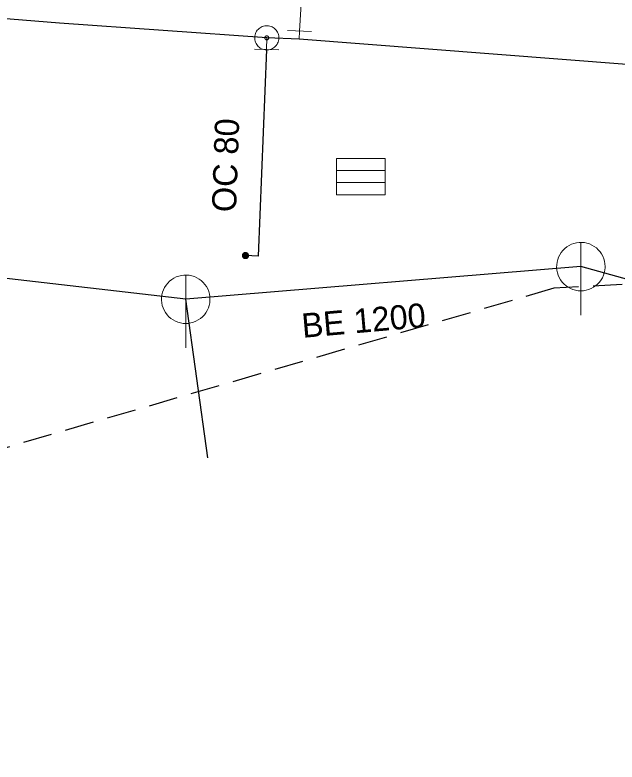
# Model space of a CAD drawing. Extents: x -725643 to -725418, y -978375 to -978221.
# Drawn here: x -725526.82 to -725501.98, y -978371.93 to -978341.11 of the extents above; entities that cross this region are included whole.
import ezdxf

# ---------------------------------------------------------------- set-up
doc = ezdxf.new("R2010")
doc.units = 0
doc.header["$LTSCALE"] = 0.4
doc.linetypes.add('MEDIUM_DASHED', pattern=[4.5, 3, -1.5])
doc.layers.add('1', color=7, linetype='Continuous')
for name, color, linetype, lineweight in [('13', 7, 'Continuous', 13), ('14', 7, 'Continuous', 25), ('17', 7, 'Continuous', 25), ('22', 7, 'Continuous', 13), ('34', 7, 'Continuous', 13), ('47', 7, 'Continuous', 13), ('63', 7, 'MEDIUM_DASHED', 25), ('9', 7, 'Continuous', 13)]:
    doc.layers.add(name, color=color, linetype=linetype, lineweight=lineweight)

msp = doc.modelspace()

# ---------------------------------------------------------------- linework, layer by layer
at = {"layer": '13'}
msp.add_line((-725515.079, -978341.78), (-725514.594, -978332.899), dxfattribs=at)
at = {"layer": '14', "lineweight": 13}
for p, q in [((-725515.094, -978342.114), (-725515.079, -978341.78)), ((-725516.432, -978342.059), (-725516.44, -978342.541))]:
    msp.add_line(p, q, dxfattribs=at)
at = {"layer": '14'}
for p, q in [((-725448.203, -978366.647), (-725503.472, -978351.493)), ((-725518.866, -978359.379), (-725519.776, -978352.842))]:
    msp.add_line(p, q, dxfattribs=at)
msp.add_lwpolyline([(-725503.472, -978351.493), (-725519.776, -978352.842), (-725535.414, -978351.036)], dxfattribs=at)
at = {"layer": '17'}
for points in [[(-725516.432, -978342.059), (-725524.989, -978341.46), (-725545.003, -978339.812), (-725548.553, -978340.172), (-725550.989, -978339.387)], [(-725476.788, -978344.909), (-725498.899, -978343.37), (-725515.094, -978342.114), (-725516.432, -978342.059)], [(-725516.44, -978342.541), (-725516.789, -978351.069), (-725517.309, -978351.039)]]:
    msp.add_lwpolyline(points, dxfattribs=at)
at = {"layer": '22'}
for p, q in [((-725513.552, -978347.532), (-725511.552, -978347.532)), ((-725513.552, -978348.032), (-725511.552, -978348.032)), ((-725503.471, -978353.493), (-725503.47, -978350.493)), ((-725519.776, -978354.842), (-725519.775, -978351.842))]:
    msp.add_line(p, q, dxfattribs=at)
for points in [[(-725513.552, -978347.032), (-725511.552, -978347.032), (-725511.552, -978348.532), (-725513.552, -978348.532)], [(-725502.471, -978351.493), (-725502.476, -978351.384), (-725502.494, -978351.276), (-725502.524, -978351.17), (-725502.564, -978351.069), (-725502.616, -978350.972), (-725502.678, -978350.882), (-725502.75, -978350.799), (-725502.83, -978350.725), (-725502.918, -978350.659), (-725503.012, -978350.604), (-725503.112, -978350.559), (-725503.217, -978350.526), (-725503.324, -978350.504), (-725503.433, -978350.494), (-725503.543, -978350.496), (-725503.651, -978350.51), (-725503.758, -978350.535), (-725503.861, -978350.572), (-725503.959, -978350.621), (-725504.051, -978350.679), (-725504.137, -978350.748), (-725504.214, -978350.825), (-725504.283, -978350.911), (-725504.342, -978351.003), (-725504.39, -978351.101), (-725504.427, -978351.204), (-725504.453, -978351.311), (-725504.467, -978351.419), (-725504.47, -978351.529), (-725504.46, -978351.638), (-725504.439, -978351.745), (-725504.405, -978351.849), (-725504.361, -978351.949), (-725504.306, -978352.044), (-725504.24, -978352.132), (-725504.166, -978352.212), (-725504.083, -978352.284), (-725503.993, -978352.346), (-725503.897, -978352.398), (-725503.795, -978352.439), (-725503.69, -978352.469), (-725503.582, -978352.487), (-725503.472, -978352.493), (-725503.363, -978352.487), (-725503.255, -978352.469), (-725503.15, -978352.44), (-725503.048, -978352.399), (-725502.951, -978352.347), (-725502.861, -978352.285), (-725502.778, -978352.214), (-725502.703, -978352.134), (-725502.638, -978352.046), (-725502.582, -978351.952), (-725502.538, -978351.852), (-725502.504, -978351.748), (-725502.482, -978351.64), (-725502.472, -978351.531)], [(-725518.776, -978352.842), (-725518.781, -978352.733), (-725518.799, -978352.625), (-725518.829, -978352.519), (-725518.869, -978352.418), (-725518.921, -978352.321), (-725518.983, -978352.231), (-725519.055, -978352.148), (-725519.135, -978352.074), (-725519.223, -978352.008), (-725519.317, -978351.953), (-725519.417, -978351.908), (-725519.522, -978351.875), (-725519.629, -978351.853), (-725519.738, -978351.843), (-725519.848, -978351.845), (-725519.956, -978351.859), (-725520.063, -978351.884), (-725520.166, -978351.921), (-725520.264, -978351.97), (-725520.356, -978352.028), (-725520.442, -978352.097), (-725520.519, -978352.174), (-725520.588, -978352.26), (-725520.647, -978352.352), (-725520.695, -978352.45), (-725520.732, -978352.553), (-725520.758, -978352.66), (-725520.772, -978352.768), (-725520.775, -978352.878), (-725520.765, -978352.987), (-725520.744, -978353.094), (-725520.71, -978353.198), (-725520.666, -978353.298), (-725520.611, -978353.393), (-725520.545, -978353.481), (-725520.471, -978353.561), (-725520.388, -978353.633), (-725520.298, -978353.695), (-725520.202, -978353.747), (-725520.1, -978353.788), (-725519.995, -978353.818), (-725519.887, -978353.836), (-725519.777, -978353.842), (-725519.668, -978353.836), (-725519.56, -978353.818), (-725519.455, -978353.789), (-725519.353, -978353.748), (-725519.256, -978353.696), (-725519.166, -978353.634), (-725519.083, -978353.563), (-725519.008, -978353.483), (-725518.943, -978353.395), (-725518.887, -978353.301), (-725518.843, -978353.201), (-725518.809, -978353.097), (-725518.787, -978352.989), (-725518.777, -978352.88)]]:
    msp.add_lwpolyline(points, close=True, dxfattribs=at)
at = {"layer": '34'}
for p, q in [((-725515.578, -978341.758), (-725514.579, -978341.802)), ((-725515.94, -978342.56), (-725516.939, -978342.52))]:
    msp.add_line(p, q, dxfattribs=at)
at = {"layer": '47'}
for points in [[(-725516.931, -978342.038), (-725516.93, -978342.09), (-725516.924, -978342.142), (-725516.912, -978342.193), (-725516.896, -978342.243), (-725516.874, -978342.291), (-725516.847, -978342.336), (-725516.816, -978342.377), (-725516.78, -978342.416), (-725516.742, -978342.45), (-725516.699, -978342.481), (-725516.653, -978342.507), (-725516.605, -978342.527), (-725516.555, -978342.543), (-725516.504, -978342.553), (-725516.452, -978342.558), (-725516.4, -978342.557), (-725516.348, -978342.551), (-725516.296, -978342.539), (-725516.247, -978342.523), (-725516.199, -978342.501), (-725516.154, -978342.474), (-725516.112, -978342.443), (-725516.073, -978342.407), (-725516.039, -978342.369), (-725516.009, -978342.326), (-725515.983, -978342.28), (-725515.962, -978342.232), (-725515.947, -978342.182), (-725515.937, -978342.131), (-725515.932, -978342.079), (-725515.933, -978342.027), (-725515.939, -978341.975), (-725515.95, -978341.923), (-725515.967, -978341.874), (-725515.989, -978341.826), (-725516.015, -978341.781), (-725516.046, -978341.739), (-725516.082, -978341.7), (-725516.121, -978341.666), (-725516.164, -978341.636), (-725516.21, -978341.61), (-725516.257, -978341.589), (-725516.308, -978341.574), (-725516.359, -978341.564), (-725516.411, -978341.559), (-725516.463, -978341.56), (-725516.515, -978341.566), (-725516.566, -978341.577), (-725516.616, -978341.594), (-725516.664, -978341.616), (-725516.709, -978341.642), (-725516.75, -978341.673), (-725516.789, -978341.709), (-725516.823, -978341.748), (-725516.854, -978341.791), (-725516.88, -978341.837), (-725516.9, -978341.884), (-725516.916, -978341.935), (-725516.926, -978341.986)], [(-725516.513, -978342.055), (-725516.514, -978342.064), (-725516.512, -978342.072), (-725516.51, -978342.08), (-725516.508, -978342.088), (-725516.504, -978342.097), (-725516.499, -978342.104), (-725516.495, -978342.111), (-725516.489, -978342.117), (-725516.482, -978342.122), (-725516.475, -978342.128), (-725516.468, -978342.132), (-725516.46, -978342.135), (-725516.452, -978342.138), (-725516.444, -978342.14), (-725516.435, -978342.14), (-725516.426, -978342.141), (-725516.418, -978342.139), (-725516.41, -978342.137), (-725516.402, -978342.135), (-725516.393, -978342.131), (-725516.386, -978342.126), (-725516.379, -978342.122), (-725516.373, -978342.116), (-725516.367, -978342.109), (-725516.362, -978342.102), (-725516.358, -978342.095), (-725516.355, -978342.087), (-725516.352, -978342.079), (-725516.35, -978342.071), (-725516.35, -978342.062), (-725516.349, -978342.053), (-725516.351, -978342.045), (-725516.353, -978342.037), (-725516.355, -978342.029), (-725516.359, -978342.02), (-725516.363, -978342.013), (-725516.368, -978342.006), (-725516.374, -978342), (-725516.381, -978341.994), (-725516.388, -978341.989), (-725516.395, -978341.985), (-725516.403, -978341.982), (-725516.411, -978341.979), (-725516.419, -978341.977), (-725516.428, -978341.977), (-725516.437, -978341.976), (-725516.445, -978341.978), (-725516.453, -978341.98), (-725516.461, -978341.982), (-725516.47, -978341.986), (-725516.477, -978341.99), (-725516.484, -978341.995), (-725516.49, -978342.001), (-725516.495, -978342.008), (-725516.501, -978342.015), (-725516.505, -978342.022), (-725516.508, -978342.03), (-725516.511, -978342.038), (-725516.513, -978342.046)]]:
    msp.add_lwpolyline(points, close=True, dxfattribs=at)
at = {"layer": '63'}
msp.add_lwpolyline([(-725440.663, -978348.762), (-725504.582, -978352.39), (-725504.582, -978352.39), (-725528.587, -978359.368), (-725528.587, -978359.368), (-725551.474, -978371.929), (-725551.474, -978371.929), (-725566.826, -978360.206), (-725566.826, -978360.206), (-725557.894, -978328.944), (-725533.89, -978332.573), (-725533.89, -978332.573), (-725529.424, -978311.918), (-725529.424, -978311.918), (-725514.351, -978316.105), (-725514.351, -978316.105), (-725517.422, -978329.502), (-725517.422, -978329.502), (-725504.582, -978332.573), (-725504.582, -978332.573), (-725495.092, -978321.408)], dxfattribs=at)
at = {"layer": '9'}
for points in [[(-725517.435, -978351.039), (-725517.435, -978351.052), (-725517.433, -978351.065), (-725517.43, -978351.078), (-725517.425, -978351.09), (-725517.419, -978351.102), (-725517.412, -978351.113), (-725517.404, -978351.123), (-725517.394, -978351.133), (-725517.384, -978351.141), (-725517.373, -978351.148), (-725517.361, -978351.154), (-725517.349, -978351.159), (-725517.336, -978351.162), (-725517.323, -978351.164), (-725517.31, -978351.166), (-725517.297, -978351.165), (-725517.284, -978351.163), (-725517.271, -978351.16), (-725517.259, -978351.155), (-725517.247, -978351.149), (-725517.236, -978351.142), (-725517.226, -978351.134), (-725517.216, -978351.124), (-725517.208, -978351.114), (-725517.201, -978351.103), (-725517.195, -978351.091), (-725517.19, -978351.079), (-725517.187, -978351.066), (-725517.185, -978351.053), (-725517.183, -978351.04), (-725517.184, -978351.027), (-725517.186, -978351.014), (-725517.189, -978351.001), (-725517.194, -978350.989), (-725517.2, -978350.977), (-725517.207, -978350.966), (-725517.215, -978350.956), (-725517.225, -978350.946), (-725517.235, -978350.938), (-725517.246, -978350.931), (-725517.258, -978350.925), (-725517.27, -978350.92), (-725517.283, -978350.917), (-725517.296, -978350.915), (-725517.309, -978350.914), (-725517.322, -978350.914), (-725517.335, -978350.916), (-725517.348, -978350.919), (-725517.36, -978350.924), (-725517.372, -978350.93), (-725517.383, -978350.937), (-725517.393, -978350.945), (-725517.403, -978350.955), (-725517.411, -978350.965), (-725517.418, -978350.976), (-725517.424, -978350.988), (-725517.429, -978351), (-725517.432, -978351.013), (-725517.434, -978351.026)], [(-725517.415, -978351.039), (-725517.416, -978351.05), (-725517.414, -978351.061), (-725517.411, -978351.072), (-725517.407, -978351.082), (-725517.402, -978351.092), (-725517.396, -978351.101), (-725517.389, -978351.11), (-725517.381, -978351.118), (-725517.372, -978351.125), (-725517.363, -978351.131), (-725517.353, -978351.136), (-725517.343, -978351.14), (-725517.332, -978351.143), (-725517.321, -978351.146), (-725517.31, -978351.146), (-725517.299, -978351.146), (-725517.288, -978351.144), (-725517.277, -978351.141), (-725517.267, -978351.137), (-725517.257, -978351.132), (-725517.248, -978351.126), (-725517.239, -978351.119), (-725517.231, -978351.111), (-725517.224, -978351.102), (-725517.218, -978351.093), (-725517.213, -978351.083), (-725517.209, -978351.073), (-725517.206, -978351.062), (-725517.204, -978351.051), (-725517.203, -978351.04), (-725517.203, -978351.029), (-725517.205, -978351.018), (-725517.208, -978351.007), (-725517.212, -978350.997), (-725517.217, -978350.987), (-725517.223, -978350.978), (-725517.23, -978350.969), (-725517.238, -978350.961), (-725517.247, -978350.954), (-725517.256, -978350.948), (-725517.266, -978350.943), (-725517.276, -978350.939), (-725517.287, -978350.936), (-725517.298, -978350.934), (-725517.309, -978350.934), (-725517.32, -978350.933), (-725517.331, -978350.935), (-725517.342, -978350.938), (-725517.352, -978350.942), (-725517.362, -978350.947), (-725517.371, -978350.953), (-725517.38, -978350.96), (-725517.388, -978350.968), (-725517.395, -978350.977), (-725517.401, -978350.986), (-725517.406, -978350.996), (-725517.41, -978351.006), (-725517.413, -978351.017), (-725517.415, -978351.028)], [(-725517.396, -978351.039), (-725517.396, -978351.048), (-725517.395, -978351.057), (-725517.392, -978351.066), (-725517.389, -978351.074), (-725517.385, -978351.082), (-725517.38, -978351.09), (-725517.374, -978351.097), (-725517.368, -978351.103), (-725517.361, -978351.109), (-725517.353, -978351.114), (-725517.345, -978351.118), (-725517.337, -978351.121), (-725517.328, -978351.124), (-725517.319, -978351.125), (-725517.31, -978351.127), (-725517.301, -978351.126), (-725517.292, -978351.125), (-725517.283, -978351.122), (-725517.275, -978351.119), (-725517.267, -978351.115), (-725517.259, -978351.11), (-725517.252, -978351.104), (-725517.246, -978351.098), (-725517.24, -978351.091), (-725517.235, -978351.083), (-725517.231, -978351.075), (-725517.228, -978351.067), (-725517.225, -978351.058), (-725517.224, -978351.049), (-725517.222, -978351.04), (-725517.223, -978351.031), (-725517.224, -978351.022), (-725517.227, -978351.013), (-725517.23, -978351.005), (-725517.234, -978350.997), (-725517.239, -978350.989), (-725517.245, -978350.982), (-725517.251, -978350.976), (-725517.258, -978350.97), (-725517.266, -978350.965), (-725517.274, -978350.961), (-725517.282, -978350.958), (-725517.291, -978350.955), (-725517.3, -978350.954), (-725517.309, -978350.953), (-725517.318, -978350.953), (-725517.327, -978350.954), (-725517.336, -978350.957), (-725517.344, -978350.96), (-725517.352, -978350.964), (-725517.36, -978350.969), (-725517.367, -978350.975), (-725517.373, -978350.981), (-725517.379, -978350.988), (-725517.384, -978350.996), (-725517.388, -978351.004), (-725517.391, -978351.012), (-725517.394, -978351.021), (-725517.395, -978351.03)], [(-725517.376, -978351.039), (-725517.376, -978351.046), (-725517.375, -978351.053), (-725517.374, -978351.06), (-725517.371, -978351.066), (-725517.368, -978351.072), (-725517.364, -978351.078), (-725517.36, -978351.084), (-725517.355, -978351.089), (-725517.349, -978351.093), (-725517.343, -978351.097), (-725517.337, -978351.1), (-725517.331, -978351.103), (-725517.324, -978351.104), (-725517.317, -978351.107), (-725517.31, -978351.107), (-725517.303, -978351.107), (-725517.296, -978351.105), (-725517.289, -978351.104), (-725517.283, -978351.101), (-725517.276, -978351.098), (-725517.271, -978351.094), (-725517.265, -978351.09), (-725517.26, -978351.085), (-725517.256, -978351.079), (-725517.252, -978351.073), (-725517.249, -978351.067), (-725517.246, -978351.061), (-725517.244, -978351.054), (-725517.243, -978351.047), (-725517.242, -978351.04), (-725517.242, -978351.033), (-725517.243, -978351.026), (-725517.245, -978351.019), (-725517.248, -978351.013), (-725517.251, -978351.006), (-725517.255, -978351.001), (-725517.259, -978350.995), (-725517.264, -978350.99), (-725517.27, -978350.986), (-725517.275, -978350.982), (-725517.282, -978350.979), (-725517.288, -978350.976), (-725517.295, -978350.974), (-725517.302, -978350.973), (-725517.309, -978350.973), (-725517.316, -978350.973), (-725517.323, -978350.973), (-725517.33, -978350.975), (-725517.336, -978350.978), (-725517.342, -978350.981), (-725517.348, -978350.985), (-725517.354, -978350.989), (-725517.359, -978350.994), (-725517.363, -978351), (-725517.367, -978351.005), (-725517.37, -978351.012), (-725517.373, -978351.018), (-725517.374, -978351.025), (-725517.376, -978351.032)], [(-725517.356, -978351.039), (-725517.356, -978351.044), (-725517.356, -978351.049), (-725517.355, -978351.054), (-725517.353, -978351.058), (-725517.351, -978351.063), (-725517.348, -978351.067), (-725517.345, -978351.07), (-725517.341, -978351.074), (-725517.338, -978351.077), (-725517.334, -978351.08), (-725517.329, -978351.082), (-725517.325, -978351.084), (-725517.32, -978351.085), (-725517.315, -978351.087), (-725517.31, -978351.087), (-725517.305, -978351.087), (-725517.3, -978351.086), (-725517.295, -978351.085), (-725517.291, -978351.083), (-725517.286, -978351.081), (-725517.282, -978351.078), (-725517.278, -978351.075), (-725517.275, -978351.071), (-725517.272, -978351.068), (-725517.269, -978351.064), (-725517.267, -978351.059), (-725517.265, -978351.055), (-725517.264, -978351.05), (-725517.263, -978351.045), (-725517.262, -978351.04), (-725517.262, -978351.035), (-725517.263, -978351.03), (-725517.264, -978351.025), (-725517.266, -978351.021), (-725517.268, -978351.016), (-725517.271, -978351.012), (-725517.274, -978351.008), (-725517.277, -978351.005), (-725517.281, -978351.002), (-725517.285, -978350.999), (-725517.29, -978350.997), (-725517.294, -978350.995), (-725517.299, -978350.994), (-725517.304, -978350.993), (-725517.309, -978350.993), (-725517.314, -978350.993), (-725517.319, -978350.994), (-725517.324, -978350.994), (-725517.328, -978350.996), (-725517.333, -978350.998), (-725517.337, -978351.001), (-725517.34, -978351.004), (-725517.344, -978351.007), (-725517.347, -978351.011), (-725517.35, -978351.015), (-725517.352, -978351.02), (-725517.354, -978351.024), (-725517.355, -978351.029), (-725517.356, -978351.034)], [(-725517.336, -978351.039), (-725517.336, -978351.042), (-725517.337, -978351.045), (-725517.336, -978351.047), (-725517.335, -978351.05), (-725517.334, -978351.053), (-725517.332, -978351.055), (-725517.33, -978351.057), (-725517.328, -978351.059), (-725517.326, -978351.061), (-725517.324, -978351.063), (-725517.321, -978351.065), (-725517.318, -978351.066), (-725517.316, -978351.066), (-725517.313, -978351.067), (-725517.31, -978351.067), (-725517.307, -978351.067), (-725517.304, -978351.067), (-725517.301, -978351.066), (-725517.299, -978351.065), (-725517.296, -978351.064), (-725517.294, -978351.062), (-725517.291, -978351.06), (-725517.289, -978351.058), (-725517.288, -978351.056), (-725517.286, -978351.054), (-725517.285, -978351.051), (-725517.283, -978351.048), (-725517.283, -978351.046), (-725517.282, -978351.043), (-725517.281, -978351.04), (-725517.282, -978351.037), (-725517.282, -978351.034), (-725517.283, -978351.031), (-725517.284, -978351.029), (-725517.285, -978351.026), (-725517.287, -978351.024), (-725517.288, -978351.021), (-725517.29, -978351.019), (-725517.293, -978351.018), (-725517.295, -978351.016), (-725517.298, -978351.015), (-725517.3, -978351.014), (-725517.303, -978351.013), (-725517.306, -978351.013), (-725517.309, -978351.012), (-725517.312, -978351.013), (-725517.315, -978351.012), (-725517.317, -978351.014), (-725517.32, -978351.014), (-725517.323, -978351.015), (-725517.325, -978351.017), (-725517.327, -978351.018), (-725517.329, -978351.02), (-725517.331, -978351.023), (-725517.333, -978351.025), (-725517.334, -978351.028), (-725517.335, -978351.03), (-725517.336, -978351.033), (-725517.336, -978351.036)], [(-725517.317, -978351.039), (-725517.317, -978351.041), (-725517.317, -978351.041), (-725517.316, -978351.041), (-725517.316, -978351.043), (-725517.317, -978351.044), (-725517.315, -978351.044), (-725517.315, -978351.044), (-725517.315, -978351.046), (-725517.315, -978351.046), (-725517.314, -978351.047), (-725517.312, -978351.047), (-725517.312, -978351.047), (-725517.312, -978351.048), (-725517.31, -978351.048), (-725517.31, -978351.048), (-725517.309, -978351.048), (-725517.308, -978351.048), (-725517.308, -978351.047), (-725517.307, -978351.047), (-725517.305, -978351.047), (-725517.305, -978351.046), (-725517.305, -978351.046), (-725517.304, -978351.045), (-725517.304, -978351.045), (-725517.302, -978351.044), (-725517.302, -978351.043), (-725517.301, -978351.042), (-725517.301, -978351.042), (-725517.301, -978351.041), (-725517.301, -978351.04), (-725517.301, -978351.039), (-725517.301, -978351.038), (-725517.301, -978351.038), (-725517.302, -978351.037), (-725517.302, -978351.036), (-725517.303, -978351.035), (-725517.303, -978351.035), (-725517.304, -978351.034), (-725517.304, -978351.034), (-725517.305, -978351.033), (-725517.306, -978351.033), (-725517.307, -978351.032), (-725517.307, -978351.032), (-725517.308, -978351.032), (-725517.309, -978351.032), (-725517.31, -978351.032), (-725517.311, -978351.032), (-725517.311, -978351.032), (-725517.312, -978351.033), (-725517.313, -978351.032), (-725517.314, -978351.034), (-725517.314, -978351.034), (-725517.315, -978351.034), (-725517.315, -978351.034), (-725517.316, -978351.036), (-725517.316, -978351.037), (-725517.316, -978351.038), (-725517.317, -978351.038), (-725517.317, -978351.039)]]:
    msp.add_lwpolyline(points, close=True, dxfattribs=at)

# ---------------------------------------------------------------- texts
at = {"layer": '1'}
for s, rotation, p in [('OC 80 ', 88, (-725517.7, -978349.262)), ('BE 1200 ', 5, (-725514.947, -978354.433))]:
    msp.add_text(s, height=1, rotation=rotation, dxfattribs=at).set_placement(p)

doc.saveas('drawing.dxf')
